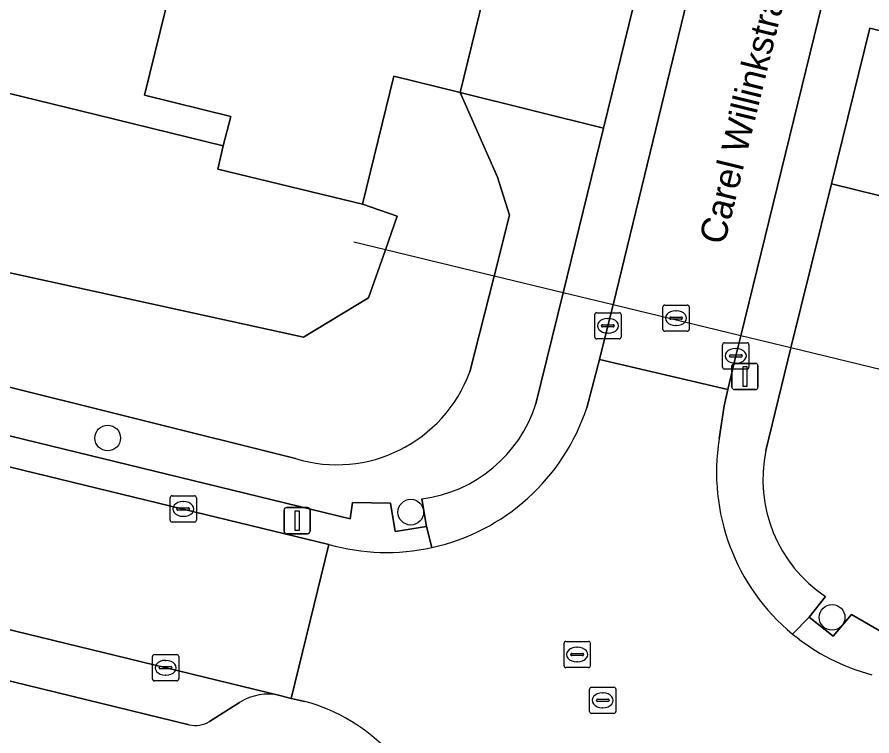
# Model space of a CAD drawing. Extents: x 163266 to 164362, y 381528 to 382286.
# Drawn here: x 163842.61 to 163875.14, y 382164.49 to 382191.83 of the extents above; entities that cross this region are included whole.
import ezdxf

# ---------------------------------------------------------------- set-up
doc = ezdxf.new("R2010")
doc.units = 0
for name, color, linetype in [('IMGEO_Boom', 7, 'Continuous'), ('IMGEO_Duiker', 7, 'Continuous'), ('IMGEO_Erf', 7, 'Continuous'), ('IMGEO_Groenvoorziening', 7, 'Continuous'), ('IMGEO_Kolk', 7, 'Continuous'), ('IMGEO_Lichtmast', 7, 'Continuous'), ('IMGEO_Openbare_ruimte_label', 7, 'Continuous'), ('IMGEO_Pand', 7, 'Continuous'), ('IMGEO_Parkeervlak_open', 7, 'Continuous'), ('IMGEO_Rijbaan_lokaal_gesloten', 7, 'Continuous'), ('IMGEO_Rijbaan_lokaal_open', 7, 'Continuous'), ('IMGEO_Rioolput', 7, 'Continuous'), ('IMGEO_Voetpad_open', 7, 'Continuous'), ('IMGEO_Waterloop', 7, 'Continuous')]:
    doc.layers.add(name, color=color, linetype=linetype)

msp = doc.modelspace()

# ---------------------------------------------------------------- linework, layer by layer
at = {"layer": 'IMGEO_Boom'}
for centre in [(163846.061, 382175.82), (163857.593, 382172.999), (163873.623, 382168.996)]:
    msp.add_circle(centre, 0.489, dxfattribs=at)
at = {"layer": 'IMGEO_Duiker'}
msp.add_lwpolyline([(163881.02, 382177.076), (163879.055, 382177.552), (163872.058, 382179.245), (163870.145, 382179.708), (163865.288, 382180.883), (163863.395, 382181.341), (163860.761, 382181.979), (163856.627, 382182.979), (163855.429, 382183.269)], dxfattribs=at)
at = {"layer": 'IMGEO_Erf'}
for points in [[(163866.059, 382211.252), (163865.221, 382207.855), (163864.154, 382208.119), (163863.7, 382206.275), (163862.002, 382206.694), (163861.291, 382203.812), (163864.592, 382202.998), (163864.525, 382202.693), (163863.99, 382202.823), (163863.155, 382199.418), (163862.085, 382199.68), (163861.633, 382197.831), (163859.94, 382198.245), (163859.232, 382195.356), (163860.934, 382194.939), (163859.471, 382188.966), (163864.927, 382187.613), (163866.368, 382193.511), (163864.412, 382193.996), (163870.173, 382217.48)], [(163882.698, 382214.3), (163876.968, 382190.935), (163875.054, 382191.408), (163873.595, 382185.486), (163879.108, 382184.137), (163880.529, 382189.974), (163882.227, 382189.552), (163882.265, 382189.707), (163882.97, 382192.602), (163881.269, 382193.016), (163881.718, 382194.862), (163880.649, 382195.122), (163881.477, 382198.522), (163880.942, 382198.652), (163880.982, 382198.819), (163884.253, 382198.009), (163884.291, 382198.164), (163884.996, 382201.059)], [(163832.364, 382210.505), (163830.154, 382205.501), (163829.36, 382205.693), (163828.663, 382202.807), (163828.625, 382202.651), (163830.626, 382202.16), (163828.52, 382193.508), (163825.231, 382194.308), (163824.955, 382193.167), (163830.417, 382191.833), (163845.022, 382188.263), (163850.46, 382186.934), (163850.742, 382188.057), (163847.466, 382188.858), (163849.627, 382197.685), (163848.364, 382197.991), (163849.305, 382201.879), (163851.61, 382201.32), (163851.897, 382205.745), (163851.46, 382205.852), (163851.536, 382206.163), (163853.694, 382205.643), (163854.403, 382208.532)]]:
    msp.add_lwpolyline(points, dxfattribs=at)
at = {"layer": 'IMGEO_Groenvoorziening'}
for points in [[(163794.602, 382193.737), (163793.926, 382191.067), (163795.941, 382190.081), (163811.747, 382185.605), (163829.348, 382180.985), (163853.204, 382175.038)], [(163859.837, 382178.336), (163860.761, 382181.979), (163861.35, 382184.302), (163860.888, 382185.749), (163859.471, 382188.966), (163856.942, 382189.584), (163855.751, 382184.72), (163857.074, 382184.258), (163856.627, 382182.979), (163855.99, 382181.153), (163853.515, 382179.66), (163840.646, 382182.469), (163829.917, 382185.005), (163815.626, 382188.515), (163803.182, 382191.841), (163801.892, 382191.922), (163797.444, 382192.463), (163794.602, 382193.737)], [(163793.926, 382191.067), (163793.111, 382187.848), (163799.313, 382186.402), (163831.956, 382178.425), (163855.29, 382172.74), (163855.378, 382173.362), (163856.815, 382173.34), (163857.005, 382172.258), (163858.186, 382172.452), (163858.019, 382173.504)], [(163853.204, 382175.038), (163829.348, 382180.985), (163811.747, 382185.605), (163795.941, 382190.081), (163793.926, 382191.067)], [(163862.354, 382177.116), (163863.395, 382181.341), (163864.927, 382187.613), (163859.471, 382188.966), (163860.888, 382185.749), (163861.35, 382184.302), (163860.761, 382181.979), (163859.837, 382178.336)], [(163877.887, 382175.562), (163878.224, 382179.635), (163880.678, 382179.716), (163881.635, 382183.522), (163879.108, 382184.137), (163873.595, 382185.486), (163872.058, 382179.245), (163871.099, 382175.35)], [(163873.369, 382169.789), (163872.751, 382169.003), (163873.663, 382168.277), (163874.366, 382169.105), (163875.652, 382168.357), (163875.451, 382167.787), (163898.631, 382162.118), (163976.491, 382143.143), (163976.694, 382144.031), (163977.58, 382143.836)]]:
    msp.add_lwpolyline(points, dxfattribs=at)
for centre, radius, start, end in [((163854.774, 382180.2), 5.396, 253.0885, 339.7856), ((163854.774, 382180.2), 5.396, 253.0885, 339.7856), ((163857.347, 382178.718), 5.257, 277.3454, 342.258), ((163876.363, 382174.255), 5.376, 168.247, 236.1636)]:
    msp.add_arc(centre, radius, start, end, dxfattribs=at)
at = {"layer": 'IMGEO_Kolk'}
for p, q in [((163864.592, 382179.662), (163864.592, 382180.514)), ((163864.667, 382180.588), (163865.519, 382180.588)), ((163865.08, 382180.368), (163865.105, 382180.368)), ((163865.593, 382180.514), (163865.593, 382179.662)), ((163864.851, 382180.082), (163864.851, 382180.094)), ((163865.289, 382180.045), (163864.891, 382180.045)), ((163864.894, 382180.131), (163865.292, 382180.131)), ((163865.335, 382180.094), (163865.335, 382180.082)), ((163865.103, 382179.808), (163865.078, 382179.808)), ((163865.519, 382179.588), (163864.667, 382179.588)), ((163869.533, 382179.444), (163870.385, 382179.444)), ((163869.458, 382178.518), (163869.458, 382179.37)), ((163869.946, 382179.224), (163869.971, 382179.224)), ((163870.459, 382179.37), (163870.459, 382178.518)), ((163869.717, 382178.938), (163869.717, 382178.95)), ((163870.155, 382178.901), (163869.757, 382178.901)), ((163869.76, 382178.987), (163870.158, 382178.987)), ((163870.201, 382178.95), (163870.201, 382178.938)), ((163870.385, 382178.444), (163869.533, 382178.444)), ((163869.969, 382178.664), (163869.944, 382178.664)), ((163848.435, 382172.694), (163848.435, 382173.546)), ((163848.51, 382173.62), (163849.362, 382173.62)), ((163849.436, 382173.546), (163849.436, 382172.694)), ((163848.923, 382173.4), (163848.948, 382173.4)), ((163848.694, 382173.114), (163848.694, 382173.126)), ((163849.132, 382173.077), (163848.734, 382173.077)), ((163848.737, 382173.163), (163849.135, 382173.163)), ((163849.178, 382173.126), (163849.178, 382173.114)), ((163849.362, 382172.62), (163848.51, 382172.62)), ((163848.946, 382172.84), (163848.921, 382172.84)), ((163847.764, 382166.653), (163847.764, 382167.505)), ((163847.839, 382167.579), (163848.691, 382167.579)), ((163848.252, 382167.359), (163848.277, 382167.359)), ((163848.765, 382167.505), (163848.765, 382166.653)), ((163848.023, 382167.073), (163848.023, 382167.085)), ((163848.461, 382167.036), (163848.063, 382167.036)), ((163848.066, 382167.122), (163848.464, 382167.122)), ((163848.507, 382167.085), (163848.507, 382167.073)), ((163848.275, 382166.799), (163848.25, 382166.799)), ((163848.691, 382166.579), (163847.839, 382166.579))]:
    msp.add_line(p, q, dxfattribs=at)
for points in [[(163864.592, 382179.662), (163864.592, 382180.514)], [(163864.667, 382180.588), (163865.519, 382180.588)], [(163865.593, 382180.514), (163865.593, 382179.662)], [(163865.519, 382179.588), (163864.667, 382179.588)], [(163869.533, 382179.444), (163870.385, 382179.444)], [(163869.458, 382178.518), (163869.458, 382179.37)], [(163870.459, 382179.37), (163870.459, 382178.518)], [(163870.385, 382178.444), (163869.533, 382178.444)], [(163848.435, 382172.694), (163848.435, 382173.546)], [(163848.51, 382173.62), (163849.362, 382173.62)], [(163849.436, 382173.546), (163849.436, 382172.694)], [(163849.362, 382172.62), (163848.51, 382172.62)], [(163847.764, 382166.653), (163847.764, 382167.505)], [(163847.839, 382167.579), (163848.691, 382167.579)], [(163848.765, 382167.505), (163848.765, 382166.653)], [(163848.691, 382166.579), (163847.839, 382166.579)]]:
    msp.add_lwpolyline(points, dxfattribs=at)
for centre, radius, start, end in [((163864.669, 382180.512), 0.0765, 91.552, 178.448), ((163864.669, 382180.512), 0.0765, 91.552, 178.448), ((163865.517, 382180.512), 0.0765, 1.552, 88.448), ((163865.517, 382180.512), 0.0765, 1.552, 88.448), ((163864.891, 382180.091), 0.0403, 85.8775, 175.7526), ((163864.888, 382180.081), 0.0366, 178.938, 274.7102), ((163865.292, 382180.088), 0.043, 264.8664, 352.4533), ((163865.296, 382180.093), 0.0386, 1.7309, 96.639), ((163864.669, 382179.664), 0.0765, 181.552, 268.448), ((163864.669, 382179.664), 0.0765, 181.552, 268.448), ((163865.517, 382179.664), 0.0765, 271.552, 358.448), ((163865.517, 382179.664), 0.0765, 271.552, 358.448), ((163869.535, 382179.368), 0.0765, 91.552, 178.448), ((163869.535, 382179.368), 0.0765, 91.552, 178.448), ((163870.383, 382179.368), 0.0765, 1.552, 88.448), ((163870.383, 382179.368), 0.0765, 1.552, 88.448), ((163869.757, 382178.947), 0.0403, 85.8775, 175.7526), ((163869.754, 382178.937), 0.0366, 178.938, 274.7102), ((163870.158, 382178.944), 0.043, 264.8664, 352.4533), ((163870.162, 382178.949), 0.0386, 1.7309, 96.639), ((163869.535, 382178.52), 0.0765, 181.552, 268.448), ((163869.535, 382178.52), 0.0765, 181.552, 268.448), ((163870.383, 382178.52), 0.0765, 271.552, 358.448), ((163870.383, 382178.52), 0.0765, 271.552, 358.448), ((163848.512, 382173.544), 0.0765, 91.552, 178.448), ((163848.512, 382173.544), 0.0765, 91.552, 178.448), ((163849.36, 382173.544), 0.0765, 1.552, 88.448), ((163849.36, 382173.544), 0.0765, 1.552, 88.448), ((163848.734, 382173.123), 0.0403, 85.8775, 175.7526), ((163848.731, 382173.113), 0.0366, 178.938, 274.7102), ((163849.135, 382173.12), 0.043, 264.8664, 352.4533), ((163849.139, 382173.125), 0.0386, 1.7309, 96.639), ((163848.512, 382172.696), 0.0765, 181.552, 268.448), ((163848.512, 382172.696), 0.0765, 181.552, 268.448), ((163849.36, 382172.696), 0.0765, 271.552, 358.448), ((163849.36, 382172.696), 0.0765, 271.552, 358.448), ((163847.841, 382167.503), 0.0765, 91.552, 178.448), ((163847.841, 382167.503), 0.0765, 91.552, 178.448), ((163848.689, 382167.503), 0.0765, 1.552, 88.448), ((163848.689, 382167.503), 0.0765, 1.552, 88.448), ((163848.063, 382167.082), 0.0403, 85.8775, 175.7526), ((163848.06, 382167.072), 0.0366, 178.938, 274.7102), ((163848.464, 382167.079), 0.043, 264.8664, 352.4533), ((163848.468, 382167.084), 0.0386, 1.7309, 96.639), ((163847.841, 382166.655), 0.0765, 181.552, 268.448), ((163847.841, 382166.655), 0.0765, 181.552, 268.448), ((163848.689, 382166.655), 0.0765, 271.552, 358.448), ((163848.689, 382166.655), 0.0765, 271.552, 358.448)]:
    msp.add_arc(centre, radius, start, end, dxfattribs=at)
for centre, major_axis, ratio, start_param, end_param in [((163865.079, 382180.088), (-0.387, 0.002), 0.722429, 4.712389, 7.853982), ((163865.104, 382180.088), (-0.39, 0.002), 0.717154, 1.570796, 4.712389), ((163869.945, 382178.944), (-0.387, 0.002), 0.722429, 4.712389, 7.853982), ((163869.97, 382178.944), (-0.39, 0.002), 0.717154, 1.570796, 4.712389), ((163848.922, 382173.12), (-0.387, 0.002), 0.722429, 4.712389, 7.853982), ((163848.947, 382173.12), (-0.39, 0.002), 0.717154, 1.570796, 4.712389), ((163848.251, 382167.079), (-0.387, 0.002), 0.722429, 4.712389, 7.853982), ((163848.276, 382167.079), (-0.39, 0.002), 0.717154, 1.570796, 4.712389)]:
    msp.add_ellipse(centre, major_axis=major_axis, ratio=ratio, start_param=start_param, end_param=end_param, dxfattribs=at)
at = {"layer": 'IMGEO_Lichtmast'}
for p, q in [((163869.813, 382177.76), (163869.813, 382178.56)), ((163869.813, 382178.56), (163869.813, 382177.76)), ((163869.913, 382178.66), (163870.703, 382178.66)), ((163870.703, 382178.66), (163869.913, 382178.66)), ((163870.803, 382178.56), (163870.803, 382177.76)), ((163870.803, 382177.76), (163870.803, 382178.56)), ((163870.703, 382177.66), (163869.913, 382177.66)), ((163869.913, 382177.66), (163870.703, 382177.66)), ((163852.772, 382172.276), (163852.772, 382173.076)), ((163852.772, 382173.076), (163852.772, 382172.276)), ((163852.872, 382173.176), (163853.662, 382173.176)), ((163853.662, 382173.176), (163852.872, 382173.176)), ((163853.762, 382173.076), (163853.762, 382172.276)), ((163853.762, 382172.276), (163853.762, 382173.076)), ((163853.662, 382172.176), (163852.872, 382172.176)), ((163852.872, 382172.176), (163853.662, 382172.176))]:
    msp.add_line(p, q, dxfattribs=at)
for points in [[(163870.233, 382178.535), (163870.383, 382178.535), (163870.383, 382177.785), (163870.233, 382177.785), (163870.233, 382178.535)], [(163853.192, 382173.051), (163853.342, 382173.051), (163853.342, 382172.301), (163853.192, 382172.301), (163853.192, 382173.051)]]:
    msp.add_lwpolyline(points, dxfattribs=at)
for centre, start, end in [((163869.913, 382178.56), 90, 180), ((163869.913, 382178.56), 90, 180), ((163870.703, 382178.56), 0, 90), ((163870.703, 382178.56), 360, 90), ((163869.913, 382177.76), 180, 270), ((163869.913, 382177.76), 180, 270), ((163870.703, 382177.76), 270, 0), ((163870.703, 382177.76), 270, 0), ((163852.872, 382173.076), 90, 180), ((163852.872, 382173.076), 90, 180), ((163853.662, 382173.076), 0, 90), ((163853.662, 382173.076), 360, 90), ((163852.872, 382172.276), 180, 270), ((163852.872, 382172.276), 180, 270), ((163853.662, 382172.276), 270, 0), ((163853.662, 382172.276), 270, 0)]:
    msp.add_arc(centre, 0.1, start, end, dxfattribs=at)
at = {"layer": 'IMGEO_Pand'}
msp.add_lwpolyline([(163859.232, 382195.356), (163849.627, 382197.685), (163847.466, 382188.858), (163850.742, 382188.057), (163850.46, 382186.934), (163850.252, 382186.054), (163855.751, 382184.72), (163856.942, 382189.584), (163859.471, 382188.966), (163860.934, 382194.939)], close=True, dxfattribs=at)
at = {"layer": 'IMGEO_Parkeervlak_open'}
for points in [[(163852.615, 382166.02), (163831.5, 382171.161), (163815.272, 382175.133)], [(163822.886, 382171.324), (163849.163, 382164.908)], [(163849.933, 382165.031), (163851.082, 382165.763)]]:
    msp.add_lwpolyline(points, dxfattribs=at)
for centre, radius, start, end in [((163852.157, 382164.054), 2.019, 76.8737, 122.16), ((163849.388, 382165.971), 1.087, 258.0531, 300.0985)]:
    msp.add_arc(centre, radius, start, end, dxfattribs=at)
at = {"layer": 'IMGEO_Rijbaan_lokaal_gesloten'}
msp.add_lwpolyline([(163816.949, 382180.901), (163809.988, 382182.603), (163801.075, 382184.7), (163799.709, 382185.043), (163798.25, 382179.249), (163798.642, 382179.156), (163805.152, 382177.618), (163815.272, 382175.133), (163831.5, 382171.161), (163852.615, 382166.02), (163853.046, 382165.915), (163854.476, 382171.773), (163848.935, 382173.119), (163832.919, 382177.001)], close=True, dxfattribs=at)
at = {"layer": 'IMGEO_Rijbaan_lokaal_open'}
msp.add_lwpolyline([(163869.958, 382178.945), (163870.145, 382179.708), (163873.864, 382194.892), (163874.335, 382196.824), (163878.406, 382213.423), (163878.49, 382213.763), (163873.597, 382214.888), (163873.566, 382214.755), (163873.007, 382212.602), (163869.494, 382198.205), (163868.973, 382196.036), (163865.288, 382180.883), (163865.094, 382180.087), (163864.773, 382178.809), (163869.659, 382177.662)], close=True, dxfattribs=at)
for points in [[(163869.332, 382175.785), (163869.514, 382177.04), (163869.659, 382177.662), (163864.773, 382178.809), (163864.288, 382176.968)], [(163854.476, 382171.773), (163853.046, 382165.915), (163853.568, 382165.798)]]:
    msp.add_lwpolyline(points, dxfattribs=at)
for centre, radius, start, end in [((163856.676, 382179.481), 8.016, 282.3887, 341.7274), ((163877.176, 382174.494), 7.95, 170.6511, 230.5134), ((163856.676, 382179.479), 8.013, 254.0675, 282.3965), ((163877.18, 382174.507), 7.962, 230.5553, 255.1354), ((163851.661, 382158.951), 7.108, 12.7722, 74.4361)]:
    msp.add_arc(centre, radius, start, end, dxfattribs=at)
at = {"layer": 'IMGEO_Rioolput'}
for p, q in [((163867.184, 382179.953), (163867.184, 382180.805)), ((163867.259, 382180.879), (163868.111, 382180.879)), ((163868.185, 382180.805), (163868.185, 382179.953)), ((163867.443, 382180.373), (163867.443, 382180.385)), ((163867.486, 382180.422), (163867.884, 382180.422)), ((163867.672, 382180.659), (163867.697, 382180.659)), ((163867.927, 382180.385), (163867.927, 382180.373)), ((163867.881, 382180.336), (163867.483, 382180.336)), ((163867.695, 382180.099), (163867.67, 382180.099)), ((163868.111, 382179.879), (163867.259, 382179.879)), ((163863.423, 382167.157), (163863.423, 382168.009)), ((163863.498, 382168.083), (163864.35, 382168.083)), ((163864.424, 382168.009), (163864.424, 382167.157)), ((163863.911, 382167.863), (163863.936, 382167.863)), ((163863.682, 382167.577), (163863.682, 382167.589)), ((163864.12, 382167.54), (163863.722, 382167.54)), ((163863.725, 382167.626), (163864.123, 382167.626)), ((163864.166, 382167.589), (163864.166, 382167.577)), ((163864.35, 382167.083), (163863.498, 382167.083)), ((163863.934, 382167.303), (163863.909, 382167.303)), ((163864.395, 382165.414), (163864.395, 382166.266)), ((163864.47, 382166.34), (163865.322, 382166.34)), ((163864.883, 382166.12), (163864.908, 382166.12)), ((163865.396, 382166.266), (163865.396, 382165.414)), ((163864.654, 382165.834), (163864.654, 382165.846)), ((163865.092, 382165.797), (163864.694, 382165.797)), ((163864.697, 382165.883), (163865.095, 382165.883)), ((163865.138, 382165.846), (163865.138, 382165.834)), ((163864.906, 382165.56), (163864.881, 382165.56)), ((163865.322, 382165.34), (163864.47, 382165.34))]:
    msp.add_line(p, q, dxfattribs=at)
for points in [[(163867.184, 382179.953), (163867.184, 382180.805)], [(163867.259, 382180.879), (163868.111, 382180.879)], [(163868.185, 382180.805), (163868.185, 382179.953)], [(163868.111, 382179.879), (163867.259, 382179.879)], [(163863.423, 382167.157), (163863.423, 382168.009)], [(163863.498, 382168.083), (163864.35, 382168.083)], [(163864.424, 382168.009), (163864.424, 382167.157)], [(163864.35, 382167.083), (163863.498, 382167.083)], [(163864.395, 382165.414), (163864.395, 382166.266)], [(163864.47, 382166.34), (163865.322, 382166.34)], [(163865.396, 382166.266), (163865.396, 382165.414)], [(163865.322, 382165.34), (163864.47, 382165.34)]]:
    msp.add_lwpolyline(points, dxfattribs=at)
for centre, radius, start, end in [((163867.261, 382180.803), 0.0765, 91.552, 178.448), ((163867.261, 382180.803), 0.0765, 91.552, 178.448), ((163868.109, 382180.803), 0.0765, 1.552, 88.448), ((163868.109, 382180.803), 0.0765, 1.552, 88.448), ((163867.483, 382180.382), 0.0403, 85.8775, 175.7526), ((163867.48, 382180.372), 0.0366, 178.938, 274.7102), ((163867.884, 382180.379), 0.043, 264.8664, 352.4533), ((163867.888, 382180.384), 0.0386, 1.7309, 96.639), ((163867.261, 382179.955), 0.0765, 181.552, 268.448), ((163867.261, 382179.955), 0.0765, 181.552, 268.448), ((163868.109, 382179.955), 0.0765, 271.552, 358.448), ((163868.109, 382179.955), 0.0765, 271.552, 358.448), ((163863.5, 382168.007), 0.0765, 91.552, 178.448), ((163863.5, 382168.007), 0.0765, 91.552, 178.448), ((163864.348, 382168.007), 0.0765, 1.552, 88.448), ((163864.348, 382168.007), 0.0765, 1.552, 88.448), ((163863.722, 382167.586), 0.0403, 85.8775, 175.7526), ((163863.719, 382167.576), 0.0366, 178.938, 274.7102), ((163864.123, 382167.583), 0.043, 264.8664, 352.4533), ((163864.127, 382167.588), 0.0386, 1.7309, 96.639), ((163863.5, 382167.159), 0.0765, 181.552, 268.448), ((163863.5, 382167.159), 0.0765, 181.552, 268.448), ((163864.348, 382167.159), 0.0765, 271.552, 358.448), ((163864.348, 382167.159), 0.0765, 271.552, 358.448), ((163864.472, 382166.264), 0.0765, 91.552, 178.448), ((163864.472, 382166.264), 0.0765, 91.552, 178.448), ((163865.32, 382166.264), 0.0765, 1.552, 88.448), ((163865.32, 382166.264), 0.0765, 1.552, 88.448), ((163864.694, 382165.843), 0.0403, 85.8775, 175.7526), ((163864.691, 382165.833), 0.0366, 178.938, 274.7102), ((163865.095, 382165.84), 0.043, 264.8664, 352.4533), ((163865.099, 382165.845), 0.0386, 1.7309, 96.639), ((163864.472, 382165.416), 0.0765, 181.552, 268.448), ((163864.472, 382165.416), 0.0765, 181.552, 268.448), ((163865.32, 382165.416), 0.0765, 271.552, 358.448), ((163865.32, 382165.416), 0.0765, 271.552, 358.448)]:
    msp.add_arc(centre, radius, start, end, dxfattribs=at)
for centre, major_axis, ratio, start_param, end_param in [((163867.671, 382180.379), (-0.387, 0.002), 0.722429, 4.712389, 7.853982), ((163867.696, 382180.379), (-0.39, 0.002), 0.717154, 1.570796, 4.712389), ((163863.91, 382167.583), (-0.387, 0.002), 0.722429, 4.712389, 7.853982), ((163863.935, 382167.583), (-0.39, 0.002), 0.717154, 1.570796, 4.712389), ((163864.882, 382165.84), (-0.387, 0.002), 0.722429, 4.712389, 7.853982), ((163864.907, 382165.84), (-0.39, 0.002), 0.717154, 1.570796, 4.712389)]:
    msp.add_ellipse(centre, major_axis=major_axis, ratio=ratio, start_param=start_param, end_param=end_param, dxfattribs=at)
at = {"layer": 'IMGEO_Voetpad_open'}
for points in [[(163870.173, 382217.48), (163864.412, 382193.996), (163866.368, 382193.511), (163864.927, 382187.613), (163863.395, 382181.341), (163862.354, 382177.116)], [(163864.288, 382176.968), (163864.773, 382178.809), (163865.094, 382180.087), (163865.288, 382180.883), (163868.973, 382196.036), (163867.035, 382196.505), (163871.405, 382214.284), (163872.36, 382214.046)], [(163871.099, 382175.35), (163872.058, 382179.245), (163873.595, 382185.486), (163875.054, 382191.408), (163876.968, 382190.935), (163882.698, 382214.3)], [(163879.179, 382212.352), (163880.134, 382212.123), (163875.763, 382194.437), (163873.864, 382194.892), (163870.145, 382179.708), (163869.958, 382178.945), (163869.659, 382177.662), (163869.514, 382177.04), (163869.332, 382175.785)], [(163858.396, 382171.652), (163858.186, 382172.452), (163857.005, 382172.258), (163856.815, 382173.34), (163855.378, 382173.362), (163855.29, 382172.74), (163831.956, 382178.425), (163799.313, 382186.402), (163793.111, 382187.848), (163792.837, 382186.765)], [(163792.837, 382186.765), (163793.404, 382186.626), (163799.709, 382185.043), (163801.075, 382184.7), (163809.988, 382182.603), (163816.949, 382180.901), (163832.919, 382177.001), (163848.935, 382173.119), (163854.476, 382171.773)], [(163858.019, 382173.504), (163858.186, 382172.452), (163858.396, 382171.652)], [(163849.163, 382164.908), (163822.886, 382171.324)], [(163872.121, 382168.358), (163872.751, 382169.003), (163873.369, 382169.789)], [(163898.631, 382162.118), (163875.451, 382167.787), (163875.652, 382168.357), (163874.366, 382169.105), (163873.663, 382168.277), (163872.751, 382169.003), (163872.121, 382168.358)], [(163851.082, 382165.763), (163849.933, 382165.031)], [(163853.568, 382165.798), (163853.046, 382165.915), (163852.615, 382166.02)]]:
    msp.add_lwpolyline(points, dxfattribs=at)
for centre, radius, start, end in [((163857.347, 382178.718), 5.257, 277.3454, 342.258), ((163856.676, 382179.481), 8.016, 282.3887, 341.7274), ((163877.176, 382174.494), 7.95, 170.6511, 230.5134), ((163876.363, 382174.255), 5.376, 168.247, 236.1636), ((163856.676, 382179.479), 8.013, 254.0675, 282.3965), ((163877.18, 382174.507), 7.962, 230.5553, 255.1354), ((163852.157, 382164.054), 2.019, 76.8737, 122.16), ((163851.661, 382158.951), 7.108, 12.7722, 74.4361), ((163849.388, 382165.971), 1.087, 258.0531, 300.0985)]:
    msp.add_arc(centre, radius, start, end, dxfattribs=at)
at = {"layer": 'IMGEO_Waterloop'}
msp.add_lwpolyline([(163840.646, 382182.469), (163853.515, 382179.66), (163855.99, 382181.153), (163856.627, 382182.979), (163857.074, 382184.258), (163855.751, 382184.72), (163850.252, 382186.054), (163850.46, 382186.934), (163845.022, 382188.263), (163830.417, 382191.833)], dxfattribs=at)

# ---------------------------------------------------------------- texts
at = {"layer": 'IMGEO_Openbare_ruimte_label'}
msp.add_text('Carel Willinkstraat', height=1, rotation=76.2279, dxfattribs=at).set_placement((163869.523, 382183.133))

doc.saveas('drawing.dxf')
